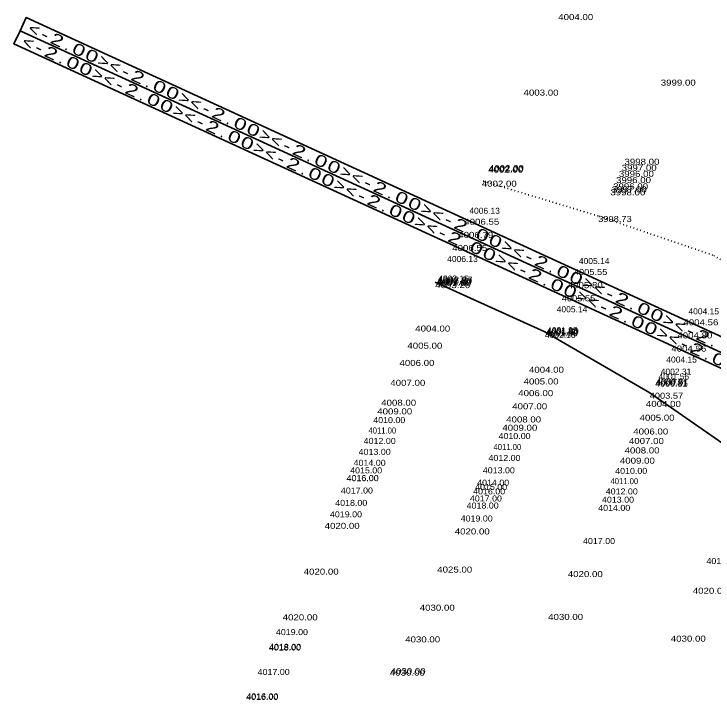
# Model space of a CAD drawing. Extents: x 49942 to 56479, y 47140 to 53283.
# Drawn here: x 49942 to 50522, y 50004 to 50573 of the extents above; entities that cross this region are included whole.
import ezdxf
from ezdxf.enums import TextEntityAlignment as Align

# ---------------------------------------------------------------- set-up
doc = ezdxf.new("R2010")
doc.units = 0
doc.header["$LTSCALE"] = 2
doc.linetypes.add('DOTTED', pattern=[1.5, 0.3, -1.2])
doc.layers.add('29', color=7, linetype='Continuous')
doc.layers.add('59', color=7, linetype='Continuous', lineweight=35)
doc.layers.add('63', color=7, linetype='Continuous', lineweight=35)

msp = doc.modelspace()

# ---------------------------------------------------------------- linework, layer by layer
at = {"layer": '59', "linetype": 'DOTTED'}
for p, q in [((50426.955, 50405.921), (50330.367, 50435.207)), ((50522.054, 50373.391), (50426.955, 50405.921)), ((50609.015, 50323.127), (50522.054, 50373.391))]:
    msp.add_line(p, q, dxfattribs=at)
at = {"layer": '59'}
for p, q in [((50382.792, 50309.696), (50291.726, 50351.013)), ((50469.673, 50259.257), (50382.792, 50309.696)), ((50553.024, 50201.131), (50469.673, 50259.257))]:
    msp.add_line(p, q, dxfattribs=at)
at = {"layer": '63'}
for points in [[(51088.959, 50048.79), (49952.321, 50570.45), (49947.316, 50559.544), (51083.954, 50037.883)], [(50910.165, 50104.44), (49942.31, 50548.638), (49947.316, 50559.544), (50915.171, 50115.346)]]:
    msp.add_lwpolyline(points, close=True, dxfattribs=at)

# ---------------------------------------------------------------- texts
at = {"layer": '29'}
for s, width, p in [('4004.00', 1.2, (50393.799, 50568.417)), ('3999.00', 1.2, (50478.868, 50514.033)), ('4003.00', 1.2, (50365.039, 50505.754)), ('3998.00', 1.2, (50448.751, 50448.411)), ('4002.00', 1.2, (50335.693, 50441.811)), ('4002.00', 1.2, (50335.986, 50442.451)), ('4002.00', 1.2, (50336.28, 50443.091)), ('3997.00', 1.2, (50446.44, 50443.376)), ('3996.00', 1.2, (50444.129, 50438.342)), ('4002.00', 1.2, (50330.367, 50430.207)), ('3996.00', 1.2, (50441.751, 50433.16)), ('3998.00', 1.2, (50437.077, 50422.976)), ('3997.00', 1.2, (50438.214, 50425.453)), ('3996.00', 1.2, (50439.351, 50427.93)), ('4006.13', 1.05, (50320.033, 50407.691)), ('3998.73', 1.15, (50426.955, 50400.921)), ('4006.55', 1.2, (50315.862, 50398.603)), ('4006.79', 1.2, (50310.857, 50387.696)), ('4006.55', 1.2, (50305.851, 50376.79)), ('4006.13', 1.05, (50301.68, 50367.702)), ('4005.14', 1.05, (50410.919, 50365.979)), ('4005.55', 1.15, (50406.747, 50356.891)), ('4002.80', 1.2, (50292.503, 50347.707)), ('4002.80', 1.2, (50292.921, 50348.616)), ('4002.80', 1.2, (50293.338, 50349.525)), ('4002.97', 1.2, (50293.781, 50350.491)), ('4003.15', 1.05, (50294.225, 50351.457)), ('4003.26', 1.2, (50291.726, 50346.013)), ('4005.80', 1.2, (50401.742, 50345.985)), ('4005.55', 1.15, (50396.737, 50335.078)), ('4005.14', 1.05, (50392.565, 50325.99)), ('4004.15', 1.05, (50501.804, 50324.268)), ('4004.56', 1.2, (50497.633, 50315.179)), ('4004.00', 1.2, (50275.188, 50309.979)), ('4001.80', 1.1, (50383.806, 50306.904)), ('4001.80', 1.1, (50384.223, 50307.813)), ('4001.88', 1.05, (50384.406, 50308.21)), ('4001.95', 1.05, (50384.588, 50308.608)), ('4002.16', 1.05, (50382.793, 50304.696)), ('4001.80', 1.1, (50383.389, 50305.995)), ('4004.80', 1.2, (50492.627, 50304.273)), ('4005.00', 1.2, (50268.65, 50295.732)), ('4004.56', 1.2, (50487.622, 50293.366)), ('4004.15', 1.05, (50483.451, 50284.278)), ('4006.00', 1.2, (50262.104, 50281.469)), ('4004.00', 1.2, (50369.521, 50275.778)), ('4002.31', 1.05, (50478.85, 50274.253)), ('4001.56', 1.05, (50476.979, 50270.177)), ('4007.00', 1.2, (50254.521, 50264.948)), ('4005.00', 1.2, (50365.072, 50266.085)), ('4000.81', 1.1, (50474.274, 50264.283)), ('4000.81', 1.1, (50474.691, 50265.192)), ('4000.81', 1.1, (50475.108, 50266.101)), ('4006.00', 1.2, (50360.623, 50256.391)), ('4003.57', 1.15, (50469.673, 50254.257)), ('4008.00', 1.2, (50246.938, 50248.426)), ('4007.00', 1.2, (50355.611, 50245.471)), ('4004.00', 1.2, (50466.558, 50247.471)), ('4009.00', 1.2, (50243.638, 50241.234)), ('4010.00', 1.1, (50240.337, 50234.042)), ('4008.00', 1.2, (50350.599, 50234.55)), ('4005.00', 1.2, (50461.301, 50236.017)), ('4009.00', 1.2, (50347.442, 50227.671)), ('4011.00', 0.95, (50236.37, 50225.398)), ('4010.00', 1.1, (50344.285, 50220.792)), ('4006.00', 1.2, (50456.044, 50224.562)), ('4012.00', 1.1, (50232.402, 50216.753)), ('4007.00', 1.2, (50452.439, 50216.707)), ('4011.00', 0.95, (50340.109, 50211.695)), ('4008.00', 1.2, (50448.834, 50208.851)), ('4013.00', 1.1, (50228.231, 50207.664)), ('4012.00', 1.1, (50335.934, 50202.597)), ('4014.00', 1.1, (50224.059, 50198.575)), ('4009.00', 1.2, (50444.939, 50200.366)), ('4015.00', 1.1, (50221.166, 50192.27)), ('4013.00', 1.1, (50331.229, 50192.345)), ('4010.00', 1.1, (50441.044, 50191.88)), ('4016.00', 1.1, (50218.202, 50185.812)), ('4016.00', 1.1, (50218.231, 50185.876)), ('4016.00', 1.1, (50218.261, 50185.941)), ('4014.00', 1.1, (50326.523, 50182.092)), ('4011.00', 0.95, (50437.137, 50183.366)), ('4017.00', 1.1, (50213.505, 50175.579)), ('4016.00', 1.1, (50323.21, 50174.873)), ('4015.00', 1.1, (50324.867, 50178.483)), ('4012.00', 1.1, (50433.216, 50174.823)), ('4017.00', 1.1, (50320.513, 50168.995)), ('4013.00', 1.1, (50430.087, 50168.004)), ('4018.00', 1.1, (50208.809, 50165.346)), ('4018.00', 1.1, (50317.815, 50163.117)), ('4014.00', 1.1, (50426.957, 50161.185)), ('4019.00', 1.1, (50204.433, 50155.811)), ('4019.00', 1.1, (50312.885, 50152.375)), ('4020.00', 1.2, (50200.053, 50146.267)), ('4020.00', 1.2, (50307.955, 50141.634)), ('4017.00', 1.1, (50414.351, 50133.718)), ('4017.00', 1.1, (50516.743, 50117.077)), ('4025.00', 1.2, (50293.44, 50110.006)), ('4020.00', 1.2, (50182.637, 50108.319)), ('4020.00', 1.2, (50401.745, 50106.252)), ('4020.00', 1.2, (50505.413, 50092.391)), ('4030.00', 1.2, (50278.924, 50078.378)), ('4020.00', 1.2, (50165.22, 50070.372)), ('4030.00', 1.2, (50385.439, 50070.723)), ('4019.00', 1.1, (50159.602, 50058.13)), ('4030.00', 1.2, (50266.843, 50052.055)), ('4030.00', 1.2, (50487.19, 50052.686)), ('4018.00', 1.1, (50153.983, 50045.887)), ('4018.00', 1.1, (50153.723, 50045.321)), ('4018.00', 1.1, (50153.853, 50045.604)), ('4017.00', 1.1, (50144.431, 50025.074)), ('4030.00', 1.2, (50254.173, 50024.45)), ('4030.00', 1.2, (50254.762, 50025.732)), ('4016.00', 1.1, (50134.912, 50004.332)), ('4016.00', 1.1, (50135.139, 50004.828))]:
    msp.add_text(s, height=5, dxfattribs=dict(at, width=width)).set_placement(p)
at = {"layer": '63'}
for s, width, p in [('<', 1.2, (49957.111, 50556.369)), ('-', 1.4, (49966.242, 50552.178)), ('2', 1.45, (49976.19, 50547.612)), ('<', 1.2, (49952.105, 50545.462)), ('-', 1.4, (49961.237, 50541.272)), ('2', 1.45, (49971.184, 50536.706)), ('0', 1.45, (49994.223, 50539.336)), ('0', 1.45, (50004.987, 50534.396)), ('0', 1.45, (49989.218, 50528.43)), ('>', 1.2, (50014.934, 50529.831)), ('0', 1.45, (49999.981, 50523.49)), ('>', 1.2, (50009.928, 50518.925)), ('<', 1.2, (50024.065, 50525.64)), ('2', 1.45, (50043.144, 50516.884)), ('<', 1.2, (50019.06, 50514.734)), ('-', 1.4, (50033.197, 50521.449)), ('-', 1.4, (50028.191, 50510.543)), ('2', 1.45, (50038.139, 50505.977)), ('0', 1.45, (50061.178, 50508.607)), ('0', 1.45, (50071.941, 50503.667)), ('0', 1.45, (50056.173, 50497.701)), ('>', 1.2, (50081.888, 50499.102)), ('0', 1.45, (50066.936, 50492.761)), ('<', 1.2, (50091.02, 50494.911)), ('>', 1.2, (50076.883, 50488.196)), ('-', 1.4, (50100.151, 50490.72)), ('2', 1.45, (50110.099, 50486.155)), ('<', 1.2, (50086.014, 50484.005)), ('0', 1.45, (50128.133, 50477.878)), ('-', 1.4, (50095.146, 50479.814)), ('2', 1.45, (50105.093, 50475.249)), ('0', 1.45, (50138.896, 50472.939)), ('0', 1.45, (50123.127, 50466.972)), ('>', 1.2, (50148.843, 50468.373)), ('0', 1.45, (50133.89, 50462.032)), ('<', 1.2, (50157.974, 50464.182)), ('>', 1.2, (50143.837, 50457.467)), ('-', 1.4, (50167.106, 50459.992)), ('2', 1.45, (50177.053, 50455.426)), ('<', 1.2, (50152.969, 50453.276)), ('0', 1.45, (50195.087, 50447.15)), ('-', 1.4, (50162.1, 50449.085)), ('2', 1.45, (50172.048, 50444.52)), ('0', 1.45, (50205.85, 50442.21)), ('0', 1.45, (50190.082, 50436.243)), ('>', 1.2, (50215.797, 50437.644)), ('0', 1.45, (50200.845, 50431.303)), ('<', 1.2, (50224.929, 50433.454)), ('>', 1.2, (50210.792, 50426.738)), ('-', 1.4, (50234.06, 50429.263)), ('2', 1.45, (50244.008, 50424.697)), ('<', 1.2, (50219.923, 50422.547)), ('-', 1.4, (50229.055, 50418.356)), ('2', 1.45, (50239.002, 50413.791)), ('0', 1.45, (50262.042, 50416.421)), ('0', 1.45, (50272.805, 50411.481)), ('0', 1.45, (50257.036, 50405.514)), ('>', 1.2, (50282.752, 50406.916)), ('0', 1.45, (50267.799, 50400.575)), ('>', 1.2, (50277.746, 50396.009)), ('<', 1.2, (50291.883, 50402.725)), ('-', 1.4, (50301.015, 50398.534)), ('2', 1.45, (50310.962, 50393.969)), ('<', 1.2, (50286.878, 50391.819)), ('0', 1.45, (50328.996, 50385.692)), ('-', 1.4, (50296.009, 50387.628)), ('2', 1.45, (50305.957, 50383.062)), ('0', 1.45, (50339.759, 50380.752)), ('0', 1.45, (50323.991, 50374.786)), ('>', 1.2, (50349.706, 50376.187)), ('0', 1.45, (50334.754, 50369.846)), ('<', 1.2, (50358.838, 50371.996)), ('>', 1.2, (50344.701, 50365.281)), ('-', 1.4, (50367.969, 50367.805)), ('2', 1.45, (50377.917, 50363.24)), ('<', 1.2, (50353.832, 50361.09)), ('0', 1.45, (50395.951, 50354.963)), ('-', 1.4, (50362.964, 50356.899)), ('2', 1.45, (50372.911, 50352.333)), ('0', 1.45, (50406.714, 50350.023)), ('0', 1.45, (50390.945, 50344.057)), ('>', 1.2, (50416.661, 50345.458)), ('0', 1.45, (50401.708, 50339.117)), ('<', 1.2, (50425.792, 50341.267)), ('>', 1.2, (50411.655, 50334.552)), ('-', 1.4, (50434.924, 50337.076)), ('2', 1.45, (50444.871, 50332.511)), ('<', 1.2, (50420.787, 50330.361)), ('-', 1.4, (50429.918, 50326.17)), ('2', 1.45, (50439.866, 50321.605)), ('0', 1.45, (50462.905, 50324.234)), ('0', 1.45, (50473.668, 50319.295)), ('>', 1.2, (50483.615, 50314.729)), ('0', 1.45, (50457.9, 50313.328)), ('0', 1.45, (50468.663, 50308.388)), ('>', 1.2, (50478.61, 50303.823)), ('<', 1.2, (50492.747, 50310.538)), ('-', 1.4, (50501.878, 50306.348)), ('2', 1.45, (50511.826, 50301.782)), ('<', 1.2, (50487.741, 50299.632)), ('2', 1.45, (50506.82, 50290.876)), ('-', 1.4, (50496.873, 50295.441)), ('0', 1.45, (50524.854, 50282.599))]:
    msp.add_text(s, height=9.6, rotation=335.347, dxfattribs=dict(at, width=width)).set_placement(p, align=Align.CENTER)
for p in [(49985.206, 50543.474), (49980.201, 50532.568), (50052.161, 50512.745), (50047.156, 50501.839), (50119.116, 50482.017), (50114.11, 50471.11), (50186.07, 50451.288), (50181.065, 50440.381), (50253.025, 50420.559), (50248.019, 50409.653), (50319.979, 50389.83), (50314.974, 50378.924), (50386.934, 50359.102), (50381.928, 50348.195), (50453.888, 50328.373), (50448.883, 50317.466), (50520.843, 50297.644), (50515.837, 50286.737)]:
    msp.add_text('.', height=9.6, rotation=335.347, dxfattribs=at).set_placement(p, align=Align.CENTER)

doc.saveas('drawing.dxf')
